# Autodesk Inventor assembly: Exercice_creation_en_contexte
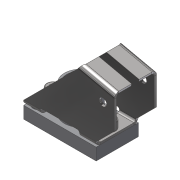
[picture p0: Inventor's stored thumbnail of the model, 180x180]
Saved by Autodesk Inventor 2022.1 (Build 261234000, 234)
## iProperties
Created: 2018-06
Part Number: Exercice_creation_en_contexte
Material: Générique
Document SubType Name: Assembly
Designer: Fabian Perrée
Mass: 105.136 g
Surface Area: 173.547 cm^2
Volume: 19.7524 cm^3
Density: 5.32267 g/cm^3
DocNumber: Exercice_creation_en_contexte.iam
Folder: .
VDS_Category: Ingénierie
Author: Fabian Perrée
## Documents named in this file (5)
- C:\Users\Fabian\Google Drive\01_Giup\01_Clients\07_ENI\Manuscrit\Fichiers_exercice\Exercice_creation_en_contexte.iam
- C:\Users\Fabian\Google Drive\01_Giup\01_Clients\07_ENI\Manuscrit\Fichiers_exercice\Chapitre_06\Exercice_creation_en_contexte\Composants\Etrier_tole.ipt
- C:\Users\Fabian\Google Drive\01_Giup\01_Clients\07_ENI\Manuscrit\Fichiers_exercice\CC\ISO 4762 - M5 x 8ISO.ipt
- C:\Users\Fabian\Google Drive\01_Giup\01_Clients\07_ENI\Manuscrit\Fichiers_exercice\Chapitre_06\Exercice_creation_en_contexte\Composants\Chapeau_capteur.ipt
- C:\Users\Fabian\Google Drive\01_Giup\01_Clients\07_ENI\Manuscrit\Fichiers_exercice\Chapitre_06\Exercice_creation_en_contexte\Composants\Bille_18.ipt
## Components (5 placed, 4 different names)
1. Etrier_tole:1 — Logement:3, Logement:4
2. Chapeau_capteur:1 — Logement:3, Logement:4
3. Bille_18:1
4. ISO 4762 M5 x 8:1
5. ISO 4762 M5 x 8:2
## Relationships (2: Insert 2)
- Logement:3 [Insert]: Etrier_tole:1 ↔ Chapeau_capteur:1
- Logement:4 [Insert]: Etrier_tole:1 ↔ Chapeau_capteur:1
